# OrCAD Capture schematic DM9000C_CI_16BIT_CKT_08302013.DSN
size Custom; title: DAVICOM Semiconductor Inc.; rev: 1.4; note: DM9000C/CI-16bit TX AUTO-MIDX
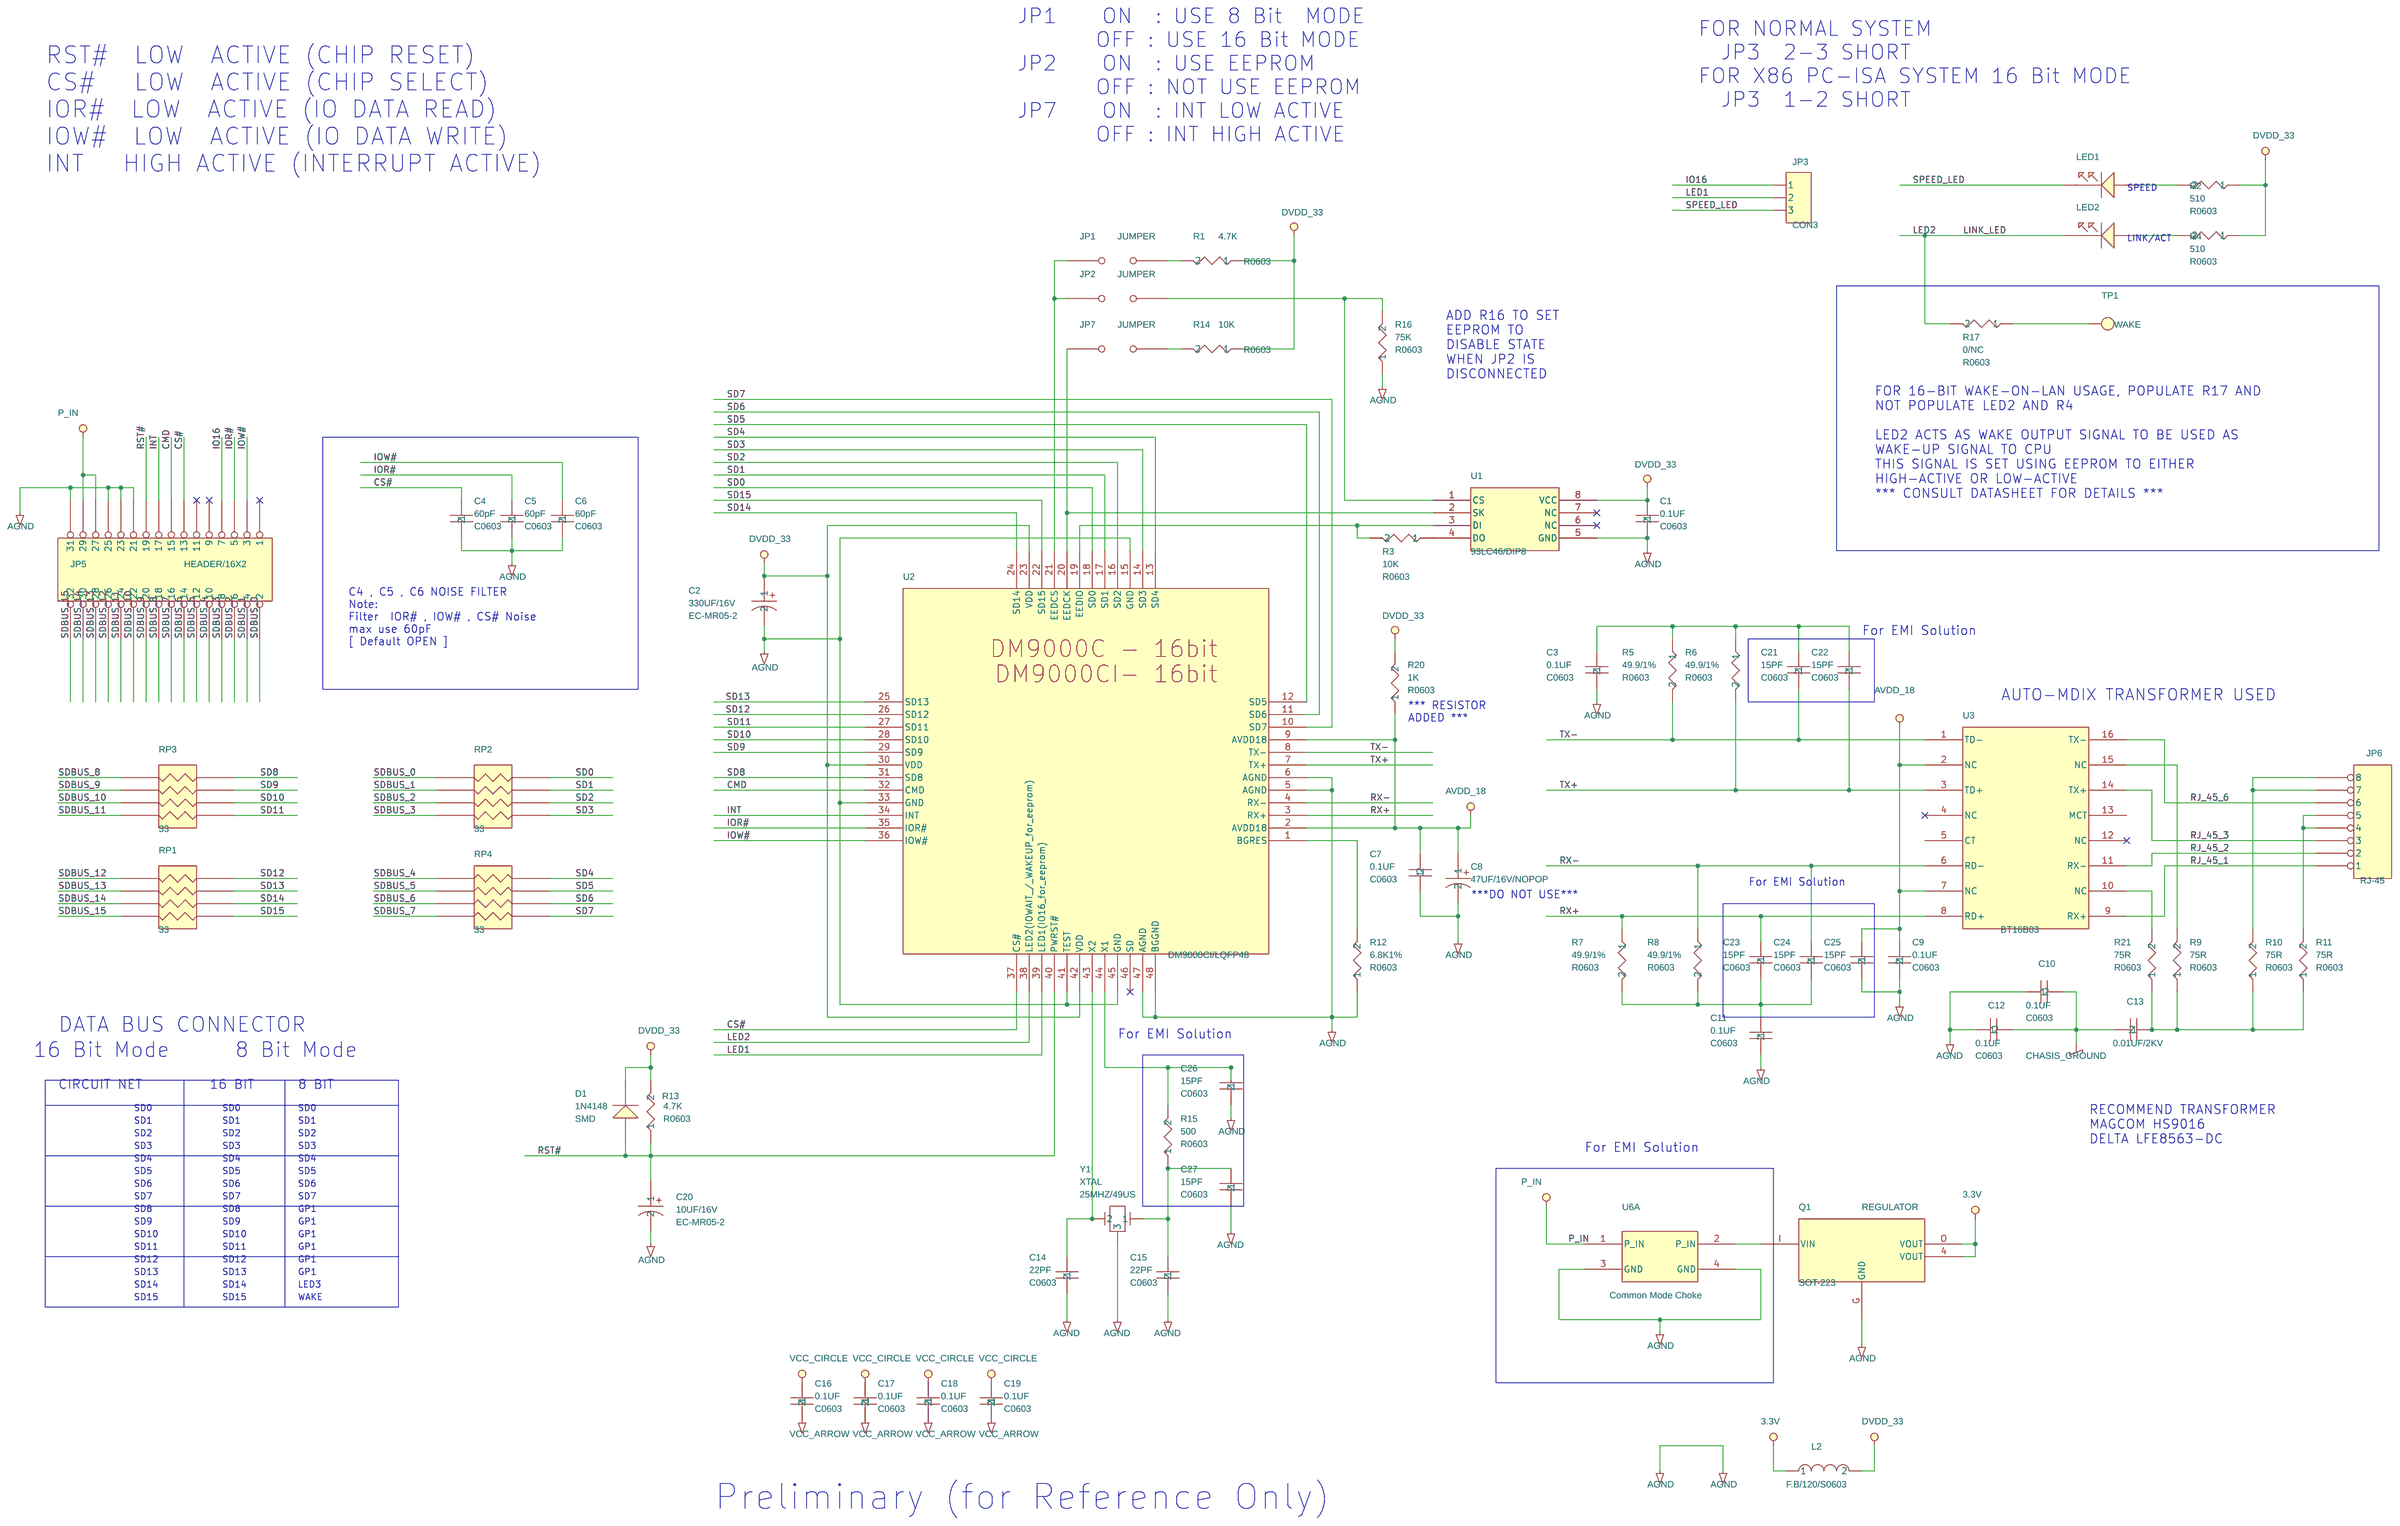
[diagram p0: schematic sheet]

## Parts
C1  0.1UF  [C0603]
C2  330UF/16V  [EC-MR05-2]
C3  0.1UF  [C0603]
C4  60pF  [C0603]
C5  60pF  [C0603]
C6  60pF  [C0603]
C7  0.1UF  [C0603]
C8  47UF/16V/NOPOP  [EC-MR05-2]
C9  0.1UF  [C0603]
C10  0.1UF  [C0603]
C11  0.1UF  [C0603]
C12  0.1UF  [C0603]
C13  0.01UF/2KV  [CAP5MM]
C14  22PF  [C0603]
C15  22PF  [C0603]
C16  0.1UF  [C0603]
C17  0.1UF  [C0603]
C18  0.1UF  [C0603]
C19  0.1UF  [C0603]
C20  10UF/16V  [EC-MR05-2]
C21  15PF  [C0603]
C22  15PF  [C0603]
C23  15PF  [C0603]
C24  15PF  [C0603]
C25  15PF  [C0603]
C26  15PF  [C0603]
C27  15PF  [C0603]
D1  1N4148  [LL34]
JP1  JUMPER  [SIP2-2.54]
JP2  JUMPER  [SIP2-2.54]
JP3  CON3  [SIP3-2.54]
JP5  HEADER/16X2  [CON16X2-2.54A]
JP6  RJ-45  [RJ45]
JP7  JUMPER  [SIP2-2.54]
L2  F.B/120/S0603  [R0603]
LED1  LED  [LED]
LED2  LED  [LED]
Q1  REGULATOR  [SOT223]
R1  4.7K  [R0603]
R2  510  [R0603]
R3  10K  [R0603]
R4  510  [R0603]
R5  49.9/1%  [R0603]
R6  49.9/1%  [R0603]
R7  49.9/1%  [R0603]
R8  49.9/1%  [R0603]
R9  75R  [R0603]
R10  75R  [R0603]
R11  75R  [R0603]
R12  6.8K1%  [R0603]
R13  4.7K  [R0603]
R14  10K  [R0603]
R15  500  [R0603]
R16  75K  [R0603]
R17  0/NC  [R0603]
R20  1K  [R0603]
R21  75R  [R0603]
RP1  33  [8P4R-B]
RP2  33  [8P4R-B]
RP3  33  [8P4R-B]
RP4  33  [8P4R-B]
TP1  WAKE
U1  93LC46/DIP8  [DIP8]
U2  DM9000CI/LQFP48  [LQFP48-0909-.5]
U3  BT16B03  [PH163539]
U6  Common Mode Choke  (section A)
Y1  25MHZ/49US  [49US+PADS]

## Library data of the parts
C1 = CAP_NP_15
C2 = CAPACITOR_POL_2
C3 = CAP_NP
C4 = CAP_NP_9
C5 = CAP_NP_19
C6 = CAP_NP_5
C7 = CAPACITOR_NON-POL_1
C8 = CAPACITOR_POL_1
C9 = CAP_NP_18
C10 = CAPACITOR_NON-POL
C11 = CAP_NP_3
C12 = CAPACITOR_NON-POL_2
C13 = CAP_NP_16
C14 = CAP_NP_4
C15 = CAP_NP_8
C16 = CAP_NP_14
C17 = CAP_NP_20
C18 = CAP_NP_1
C19 = CAP_NP_7
C20 = CAPACITOR_POL
C21 = CAP_NP_12
C22 = CAP_NP_13
C23 = CAP_NP_10
C24 = CAP_NP_6
C25 = CAP_NP_2
C26 = CAP_NP_11
C27 = CAP_NP_17
D1 = DIODE_0: 1ST PART FIELD: SMD
JP1 JP2 JP7 = JUMPER
JP3 = CON3
JP5 = HEADER_16X2
JP6 = HEADER_8_1: 1ST PART FIELD: RJ8-45
L2 = INDUCTOR
LED1 LED2 = LED
Q1 = G910_1: 1ST PART FIELD: SOT-223
R1 = R_18
R2 = R
R3 = R_8
R4 = R_6
R5 = R_9
R6 = R_5
R7 = R_10
R8 = R_15
R9 = R_17
R10 = R_4
R11 = R_2
R12 = R_11
R13 = R_14
R14 = R_3
R15 = R_7
R16 = R_12
R17 = R_13
R20 = R_16
R21 = R_1
RP1-RP4 = RESISTOR_DIP_4_0
TP1 = T_POINT_R
U1 = 9346
U2 = DM9118_36
U3 = MIM_0: 1ST PART FIELD: YCL0303
U6 = EL7272C-N_1
Y1 = CRYSTAL_0: 1ST PART FIELD: XTAL

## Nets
3.3V: L2.1 Q1.4(VOUT) Q1.O(VOUT)
AGND: C1.2 C2.2 C3.2 C4.2 C5.2 C6.2 C7.1 C8.2 C9.2 C10.1 C11.2 C12.1 C14.2 C15.2 C16.2 C17.2 C18.2 C19.2 C20.2 C25.2 C26.2 C27.2 JP5.21 JP5.23 JP5.25 JP5.31 Q1.G(GND) R12.1 R16.1 U1.5(GND) U2.5(AGND) U2.6(AGND) U2.15(GND) U2.33(GND) U2.41(TEST) U2.45(GND) U2.47(AGND) U2.48(BGGND) U6.3(GND) U6.4(GND) Y1.3
AVDD_18: C7.2 C8.1 C9.1 C25.1 R20.1 U2.2(AVDD18) U2.9(AVDD18) U3.2(NC) U3.7(NC)
DVDD_33: C1.1 C2.1 C16.1 C17.1 C18.1 C19.1 D1.C L2.2 R1.1 R2.1 R4.1 R13.2 R14.1 R20.2 U1.8(VCC) U2.23(VDD) U2.30(VDD) U2.42(VDD)
CHASIS_GROUND: C10.2 C12.2 C13.2
CMD: JP5.15 U2.32(CMD)
CS#: C4.1 JP5.13 U2.37(CS#)
INT: JP5.17 U2.34(INT)
IO16: JP3.1 JP5.7
IOR#: C5.1 JP5.5 U2.35(IOR#)
IOW#: C6.1 JP5.3 U2.36(IOW#)
LED1: JP3.2 U2.39(LED1(IO16_for_eeprom))
LED2: LED2.2 R17.2 U2.38(LED2(IOWAIT_/_WAKEUP_for_eeprom))
P_IN_5V: JP5.27 JP5.29 U6.1(P_IN)
RJ_45_1: JP6.1 U3.9(RX+)
RJ_45_2: JP6.2 U3.11(RX-)
RJ_45_3: JP6.3 U3.14(TX+)
RJ_45_6: JP6.6 U3.16(TX-)
RST#: C20.1 D1.A JP5.19 R13.1 U2.40(PWRST#)
RX+: C23.1 R7.1 U2.3(RX+) U3.8(RD+)
RX-: C24.1 R8.1 U2.4(RX-) U3.6(RD-)
SD0: RP2.8 U2.18(SD0)
SD1: RP2.6 U2.17(SD1)
SD2: RP2.4 U2.16(SD2)
SD3: RP2.2 U2.14(SD3)
SD4: RP4.2 U2.13(SD4)
SD5: RP4.4 U2.12(SD5)
SD6: RP4.6 U2.11(SD6)
SD7: RP4.8 U2.10(SD7)
SD8: RP3.8 U2.31(SD8)
SD9: RP3.6 U2.29(SD9)
SD10: RP3.4 U2.28(SD10)
SD11: RP3.2 U2.27(SD11)
SD12: RP1.8 U2.26(SD12)
SD13: RP1.6 U2.25(SD13)
SD14: RP1.4 U2.24(SD14)
SD15: RP1.2 U2.22(SD15)
SDBUS_0: JP5.2 RP2.7
SDBUS_1: JP5.4 RP2.5
SDBUS_2: JP5.6 RP2.3
SDBUS_3: JP5.8 RP2.1
SDBUS_4: JP5.10 RP4.1
SDBUS_5: JP5.12 RP4.3
SDBUS_6: JP5.14 RP4.5
SDBUS_7: JP5.16 RP4.7
SDBUS_8: JP5.18 RP3.7
SDBUS_9: JP5.20 RP3.5
SDBUS_10: JP5.22 RP3.3
SDBUS_11: JP5.24 RP3.1
SDBUS_12: JP5.26 RP1.7
SDBUS_13: JP5.28 RP1.5
SDBUS_14: JP5.30 RP1.3
SDBUS_15: JP5.32 RP1.1
SPEED_LED: JP3.3 LED1.2
TX+: C22.2 R6.2 U2.7(TX+) U3.3(TD+)
TX-: C21.2 R5.2 U2.8(TX-) U3.1(TD-)
N11670156: R3.2 U1.3(DI) U2.19(EEDIO)
N11670184: C26.1 R15.2 U2.44(X1)
N11671304: LED2.1 R4.2
N11671308: LED1.1 R2.2
N11680184: R9.2 U3.15(NC)
N11680188: C13.1 R9.1 R10.1 R11.1 R21.1
N11680208: C3.1 C21.1 C22.1 R5.1 R6.1
N11680272: C11.1 C23.2 C24.2 R7.2 R8.2
N11680364: JP6.7 JP6.8 R10.2
N11680368: JP6.4 JP6.5 R11.2
N16765406: JP2.2 R16.2 U1.1(CS)
N16773825: C14.1 U2.43(X2) Y1.2
N16804652: JP7.1 U1.2(SK) U2.20(EEDCK)
N16820817: JP1.1 JP2.1 U2.21(EEDCS)
N16827223: JP1.2 R1.2
N16845050: C15.1 C27.1 R15.1 Y1.1
N16846552: Q1.I(VIN) U6.2(P_IN)
N16858157: JP7.2 R14.2
N16875453: R12.2 U2.1(BGRES)
N16879159: R3.1 U1.4(DO)
N16879218: R17.1 TP1.1(TP)
N16887113: R21.2 U3.10(NC)

Not connected (* = marked no-connect by the designer): JP5 1* 9* 11*; U1 6(NC)* 7(NC)*; U2 46(SD)*; U3 4(NC)* 5(CT) 12(NC)* 13(MCT)

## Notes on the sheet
- JP1    ON  : USE 8 Bit  MODE
         OFF : USE 16 Bit MODE
  JP2    ON  : USE EEPROM
         OFF : NOT USE EEPROM
  JP7    ON  : INT LOW ACTIVE
         OFF : INT HIGH ACTIVE
- FOR NORMAL SYSTEM
    JP3  2-3 SHORT
  FOR X86 PC-ISA SYSTEM 16 Bit MODE
    JP3  1-2 SHORT
- RST#  LOW  ACTIVE (CHIP RESET)
  CS#   LOW  ACTIVE (CHIP SELECT)
  IOR#  LOW  ACTIVE (IO DATA READ)
  IOW#  LOW  ACTIVE (IO DATA WRITE)
  INT   HIGH ACTIVE (INTERRUPT ACTIVE)
- SPEED
- LINK/ACT
- ADD R16 TO SET
  EEPROM TO
  DISABLE STATE
  WHEN JP2 IS
  DISCONNECTED
- FOR 16-BIT WAKE-ON-LAN USAGE, POPULATE R17 AND
  NOT POPULATE LED2 AND R4
  LED2 ACTS AS WAKE OUTPUT SIGNAL TO BE USED AS
  WAKE-UP SIGNAL TO CPU
  THIS SIGNAL IS SET USING EEPROM TO EITHER
  HIGH-ACTIVE OR LOW-ACTIVE
  *** CONSULT DATASHEET FOR DETAILS ***
- C4 , C5 , C6 NOISE FILTER
  Note:
  Filter  IOR# , IOW# , CS# Noise
  max use 60pF
  [ Default OPEN ]
- For EMI Solution
- AUTO-MDIX TRANSFORMER USED
- *** RESISTOR
  ADDED ***
- ***DO NOT USE***
- For EMI Solution
- DATA BUS CONNECTOR
- For EMI Solution
- 16 Bit Mode
- 8 Bit Mode
- CIRCUIT NET
- 16 BIT
- 8 BIT
- SD0
- SD0
- SD0
- RECOMMEND TRANSFORMER
  MAGCOM HS9016
  DELTA LFE8563-DC
- SD1
- SD2
- SD1
- SD2
- SD1
- SD2
- SD3
- SD3
- SD3
- For EMI Solution
- SD4
- SD4
- SD4
- SD5
- SD5
- SD5
- SD6
- SD6
- SD6
- SD7
- SD7
- SD7
- SD8
- SD9
- SD8
- SD9
- GP1
- GP1
- SD10
- SD10
- GP1
- SD11
- SD11
- GP1
- SD12
- SD12
- GP1
- SD13
- SD13
- GP1
- SD14
- SD15
- SD14
- SD15
- LED3
- WAKE
- Preliminary (for Reference Only)
